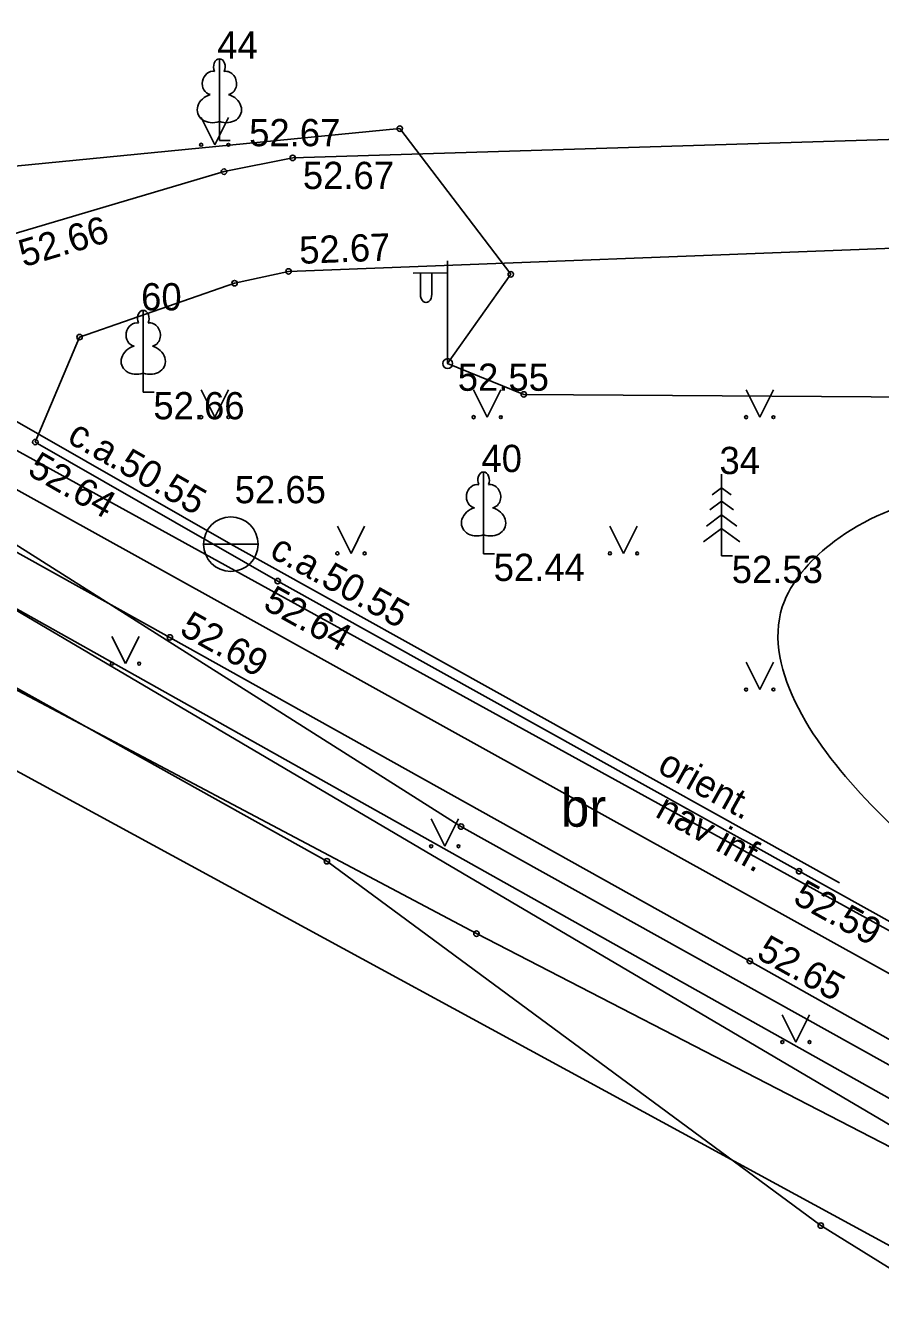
# Model space of a CAD drawing. Extents: x 619806 to 620082, y 405176 to 405386.
# Drawn here: x 619836.53 to 619852.21, y 405268.71 to 405292.19 of the extents above; entities that cross this region are included whole.
import ezdxf

# ---------------------------------------------------------------- set-up
doc = ezdxf.new("R2010")
doc.units = 0
for name, color, linetype in [('APGR_SARK_####_####_#', 7, 'Continuous'), ('APGS_ELEM_####_####_#', 7, 'Continuous'), ('APGS_VADP_ZSPR_####_#', 7, 'Continuous'), ('CELI_CMAL_####_####_#', 7, 'Continuous'), ('CELI_CSEG_####_TKST_#', 7, 'Continuous'), ('ELEK_VADP_ZSPR_####_#', 7, 'Continuous'), ('RAMI_UZMR_####_####_#', 7, 'Continuous'), ('RELJ_AATZ_####_TKST_#', 7, 'Continuous'), ('RELJ_ELEM_####_####_#', 7, 'Continuous'), ('RELJ_HORZ_PAMT_####_#', 7, 'Continuous'), ('ROBZ_UZMR_####_####_#', 7, 'Continuous'), ('SAKK_KKAN_####_####_#', 7, 'Continuous'), ('SAKT_VADP_KABE_####_#', 7, 'Continuous'), ('TERT_DIAM_####_TKST_#', 7, 'Continuous'), ('TERT_ELEM_####_####_#', 7, 'Continuous'), ('UDTK_ELEM_####_####_#', 7, 'Continuous'), ('UDTK_ELEM_####_TKST_#', 7, 'Continuous'), ('UDTK_VADP_UDEN_####_#', 7, 'Continuous'), ('UDTK_VADP_UDEN_TKST_#', 7, 'Continuous')]:
    doc.layers.add(name, color=color, linetype=linetype)

msp = doc.modelspace()

# ---------------------------------------------------------------- linework, layer by layer
at = {"layer": 'APGR_SARK_####_####_#'}
msp.add_lwpolyline([(619990.053, 405197.403), (619966.019, 405209.806), (619941.986, 405222.21), (619880.273, 405256.839), (619818.56, 405291.467)], dxfattribs=at)
at = {"layer": 'APGS_ELEM_####_####_#'}
for p, q in [((619844.273, 405285.984), (619844.273, 405287.867)), ((619844.273, 405287.651), (619843.638, 405287.646)), ((619843.773, 405287.647), (619843.773, 405287.255)), ((619843.983, 405287.649), (619843.983, 405287.255))]:
    msp.add_line(p, q, dxfattribs=at)
msp.add_circle((619844.273, 405285.984), 0.09, dxfattribs=at)
msp.add_ellipse((619843.878, 405287.255), major_axis=(0, 0.151), ratio=0.695971, start_param=1.570796, end_param=4.712389, dxfattribs=at)
at = {"layer": 'APGS_VADP_ZSPR_####_#'}
for points in [[(619889.151, 405287.633), (619888.839, 405287.188), (619868.564, 405286.313), (619868.359, 405286.853), (619868.361, 405286.315), (619854.776, 405285.354), (619845.67, 405285.418), (619844.273, 405285.984), (619845.432, 405287.623), (619843.395, 405290.297), (619835.199, 405289.5), (619828.336, 405290.779), (619827.279, 405290.766)], [(619827.279, 405290.766), (619828.233, 405290.484), (619831.689, 405284.666), (619835.137, 405280.637), (619844.802, 405275.519), (619857.367, 405269.037), (619864.044, 405264.897), (619871.373, 405258.791), (619881.17, 405253.384), (619884.232, 405252.778), (619898.622, 405244.594), (619910.805, 405239.254), (619917.273, 405236.249), (619923.426, 405231.863), (619936.8, 405224.512), (619938.618, 405223.547), (619972.929, 405204.127)]]:
    msp.add_lwpolyline(points, dxfattribs=at)
at = {"layer": 'CELI_CMAL_####_####_#'}
for points in [[(619901.141, 405301.297), (619895.285, 405291.495), (619886.767, 405291.266), (619876.357, 405290.867), (619868.929, 405290.713), (619868.879, 405291.869), (619865.764, 405291.699), (619865.807, 405290.556), (619863.458, 405290.505), (619853.554, 405290.137), (619841.43, 405289.76), (619840.169, 405289.507), (619836.17, 405288.32), (619833.502, 405287.788), (619826.905, 405297.999), (619827.372, 405299.068), (619837.906, 405304.107), (619846.534, 405308.229), (619856.914, 405313.201), (619868.255, 405318.592), (619880.738, 405324.67), (619889.516, 405328.858), (619904.867, 405336.211)], [(619859.084, 405268.056), (619860.53, 405268.999), (619849.818, 405275.016), (619839.176, 405280.957), (619830.556, 405285.755), (619828.304, 405287.001), (619823.674, 405289.625), (619822.58, 405290.149), (619821.807, 405290.092)], [(619836.706, 405284.543), (619837.518, 405286.469), (619840.363, 405287.459), (619841.354, 405287.676), (619853.093, 405288.124), (619867.164, 405288.545), (619875.272, 405288.879), (619893.318, 405289.417), (619886.606, 405285.41), (619875.838, 405278.602), (619871.198, 405275.77), (619866.813, 405272.975), (619862.385, 405270.176), (619850.722, 405276.664), (619841.154, 405281.99), (619836.706, 405284.543)]]:
    msp.add_lwpolyline(points, dxfattribs=at)
at = {"layer": 'ELEK_VADP_ZSPR_####_#'}
for points in [[(619827.133, 405291.802), (619827.743, 405291.898), (619828.762, 405290.038), (619831.425, 405286.162), (619834.68, 405283.716), (619844.517, 405277.484), (619856.454, 405270.832), (619868.451, 405264.196), (619879.269, 405258.357), (619888.402, 405252.405), (619901.725, 405245.908), (619900.354, 405242.567), (619899.734, 405241.465)], [(619827.133, 405291.802), (619827.704, 405291.789), (619828.409, 405290.12), (619829.758, 405288.499), (619829.214, 405285.683), (619831.9, 405284.021), (619834.586, 405281.015), (619842.057, 405276.848), (619851.121, 405270.16), (619862.697, 405262.983), (619874.919, 405256.089), (619882.875, 405253.63), (619881.737, 405251.572)]]:
    msp.add_lwpolyline(points, dxfattribs=at)
at = {"layer": 'RAMI_UZMR_####_####_#'}
msp.add_lwpolyline([(619874.687, 405324.979), (619926.719, 405349.544), (619966.669, 405369.042), (620021.738, 405292.03), (620049.703, 405275.476), (620026.189, 405242.287), (620012.147, 405222.917), (619996.603, 405200.928), (619989.997, 405199.173), (619982.328, 405199.155), (619922.669, 405233.014), (619882.137, 405255.756), (619859.084, 405268.056), (619820.646, 405290.715), (619813.744, 405295.206), (619820.645, 405298.752)], close=True, dxfattribs=at)
at = {"layer": 'RELJ_ELEM_####_####_#'}
for centre in [(619843.395, 405290.297), (619841.43, 405289.76), (619840.169, 405289.507), (619841.354, 405287.676), (619845.432, 405287.623), (619840.363, 405287.459), (619837.518, 405286.469), (619845.67, 405285.418), (619836.706, 405284.543), (619841.154, 405281.99), (619839.176, 405280.957), (619844.517, 405277.484), (619842.057, 405276.848), (619850.722, 405276.664), (619844.802, 405275.519), (619849.818, 405275.016), (619851.121, 405270.16)]:
    msp.add_circle(centre, 0.05, dxfattribs=at)
at = {"layer": 'RELJ_HORZ_PAMT_####_#'}
msp.add_spline([(619862.12, 405283.56), (619866.347, 405284.072), (619870.176, 405284.36), (619872.57, 405283.726), (619875.877, 405282.305), (619878.056, 405282.964), (619882.355, 405286.311), (619884.573, 405287.696), (619885.242, 405286.98), (619884.066, 405285.895), (619878.235, 405281.695), (619876.552, 405280.844), (619873.556, 405282.133), (619871.504, 405282.549), (619870.25, 405280.5), (619867.776, 405275.169), (619866.854, 405274.292), (619864.131, 405274.836), (619862.108, 405272.722), (619860.734, 405271.784), (619858.644, 405272.772), (619855.468, 405275.204), (619851.943, 405277.991), (619850.454, 405281.625), (619851.371, 405282.722), (619855.287, 405283.69), (619860.401, 405283.354), (619862.12, 405283.56)], degree=3, dxfattribs=at)
at = {"layer": 'ROBZ_UZMR_####_####_#'}
msp.add_line((619862.459, 405270.018), (619818.193, 405294.391), dxfattribs=at)
at = {"layer": 'SAKK_KKAN_####_####_#'}
msp.add_lwpolyline([(619816.151, 405294.73), (619816.825, 405294), (619832.922, 405285.576), (619895.115, 405251.073), (619918.714, 405238.138)], dxfattribs=at)
at = {"layer": 'SAKT_VADP_KABE_####_#'}
msp.add_lwpolyline([(619817.668, 405301.762), (619818.308, 405291.251), (619820.058, 405288.244), (619821.78, 405286.435), (619865.996, 405262.382), (619894.538, 405246.913), (619928.954, 405228.717), (619988.18, 405195.595)], dxfattribs=at)
at = {"layer": 'TERT_ELEM_####_####_#'}
for p, q in [((619839.75, 405290.5), (619840, 405290)), ((619840, 405290), (619840.25, 405290.5)), ((619840.084, 405290.427), (619840.084, 405290.08)), ((619840.084, 405290.08), (619840.284, 405290.08)), ((619838.687, 405285.808), (619838.687, 405285.461)), ((619838.687, 405285.461), (619838.887, 405285.461)), ((619839.75, 405285.5), (619840, 405285)), ((619840, 405285), (619840.25, 405285.5)), ((619844.75, 405285.5), (619845, 405285)), ((619845, 405285), (619845.25, 405285.5)), ((619849.75, 405285.5), (619850, 405285)), ((619850, 405285), (619850.25, 405285.5)), ((619849.301, 405283.955), (619849.301, 405282.455)), ((619849.301, 405283.705), (619849.125, 405283.577)), ((619849.301, 405283.705), (619849.475, 405283.577)), ((619849.301, 405283.455), (619849.085, 405283.297)), ((619849.301, 405283.455), (619849.517, 405283.297)), ((619849.301, 405283.205), (619849.023, 405283.001)), ((619849.301, 405283.205), (619849.579, 405283.001)), ((619842.25, 405283), (619842.5, 405282.5)), ((619842.5, 405282.5), (619842.75, 405283)), ((619844.932, 405282.84), (619844.932, 405282.493)), ((619847.25, 405283), (619847.5, 405282.5)), ((619847.5, 405282.5), (619847.75, 405283)), ((619849.301, 405282.955), (619848.969, 405282.711)), ((619849.301, 405282.955), (619849.635, 405282.711)), ((619844.932, 405282.493), (619845.132, 405282.493)), ((619849.301, 405282.455), (619849.501, 405282.455)), ((619838.111, 405280.976), (619838.361, 405280.476)), ((619838.361, 405280.476), (619838.611, 405280.976)), ((619849.75, 405280.5), (619850, 405280)), ((619850, 405280), (619850.25, 405280.5)), ((619843.971, 405277.624), (619844.221, 405277.124)), ((619844.221, 405277.124), (619844.471, 405277.624)), ((619850.414, 405274.029), (619850.664, 405273.529)), ((619850.664, 405273.529), (619850.914, 405274.029))]:
    msp.add_line(p, q, dxfattribs=at)
for points in [[(619840.084, 405291.58), (619840.084, 405290.427)], [(619840.174, 405291.348), (619840.173, 405291.349)], [(619838.687, 405286.961), (619838.687, 405285.808)], [(619838.777, 405286.729), (619838.776, 405286.73)], [(619844.932, 405283.993), (619844.932, 405282.84)], [(619845.022, 405283.761), (619845.021, 405283.762)]]:
    msp.add_lwpolyline(points, dxfattribs=at)
for centre, radius in [((619839.75, 405290), 0.028), ((619840.25, 405290), 0.0263), ((619839.75, 405285), 0.028), ((619840.25, 405285), 0.0263), ((619844.75, 405285), 0.028), ((619845.25, 405285), 0.0263), ((619849.75, 405285), 0.028), ((619850.25, 405285), 0.0263), ((619842.25, 405282.5), 0.028), ((619842.75, 405282.5), 0.0263), ((619847.25, 405282.5), 0.028), ((619847.75, 405282.5), 0.0263), ((619838.111, 405280.475), 0.028), ((619838.611, 405280.475), 0.0263), ((619849.75, 405280), 0.028), ((619850.25, 405280), 0.0263), ((619843.971, 405277.123), 0.028), ((619844.471, 405277.123), 0.0263), ((619850.414, 405273.528), 0.028), ((619850.914, 405273.528), 0.0263)]:
    msp.add_circle(centre, radius, dxfattribs=at)
for centre, major_axis, ratio, start_param, end_param in [((619840.084, 405291.43), (0, -0.15), 0.707107, 3.14537, 5.287485), ((619840.084, 405291.43), (0, -0.15), 0.707107, 0.995701, 3.137816), ((619839.956, 405291.135), (-0.039, -0.212), 0.861323, 3.141593, 6.283185), ((619840.212, 405291.135), (0.039, -0.212), 0.861323, 0, 3.141593), ((619839.994, 405290.673), (0.307, 0.095), 0.814445, 1.570796, 4.752015), ((619840.174, 405290.673), (-0.307, 0.095), 0.814445, 1.531171, 4.712389), ((619838.687, 405286.811), (0, -0.15), 0.707107, 3.14537, 5.287485), ((619838.687, 405286.811), (0, -0.15), 0.707107, 0.995701, 3.137816), ((619838.559, 405286.516), (-0.039, -0.212), 0.861323, 3.141593, 6.283185), ((619838.815, 405286.516), (0.039, -0.212), 0.861323, 0, 3.141593), ((619838.597, 405286.054), (0.307, 0.095), 0.814445, 1.570796, 4.752015), ((619838.777, 405286.054), (-0.307, 0.095), 0.814445, 1.531171, 4.712389), ((619844.804, 405283.548), (-0.039, -0.212), 0.861323, 3.141593, 6.283185), ((619844.932, 405283.843), (0, -0.15), 0.707107, 3.14537, 5.287485), ((619844.932, 405283.843), (0, -0.15), 0.707107, 0.995701, 3.137816), ((619845.06, 405283.548), (0.039, -0.212), 0.861323, 0, 3.141593), ((619844.842, 405283.086), (0.307, 0.095), 0.814445, 1.570796, 4.752015), ((619845.022, 405283.086), (-0.307, 0.095), 0.814445, 1.531171, 4.712389)]:
    msp.add_ellipse(centre, major_axis=major_axis, ratio=ratio, start_param=start_param, end_param=end_param, dxfattribs=at)
at = {"layer": 'UDTK_ELEM_####_####_#'}
msp.add_line((619839.794, 405282.668), (619840.794, 405282.668), dxfattribs=at)
msp.add_circle((619840.294, 405282.668), 0.5, dxfattribs=at)
at = {"layer": 'UDTK_VADP_UDEN_####_#'}
for points in [[(619840.294, 405282.668), (619831.461, 405287.722)], [(619840.294, 405282.668), (619851.461, 405276.454)]]:
    msp.add_lwpolyline(points, dxfattribs=at)

# ---------------------------------------------------------------- texts
at = {"layer": 'CELI_CSEG_####_TKST_#'}
msp.add_text('br', height=0.7, dxfattribs=at).set_placement((619846.352, 405277.482))
at = {"layer": 'RELJ_AATZ_####_TKST_#'}
for s, p in [(' 52.67', (619840.445, 405289.974)), (' 52.67', (619841.43, 405289.188)), (' 52.55', (619844.273, 405285.484)), (' 52.66', (619838.687, 405284.961)), (' 52.44', (619844.932, 405281.993)), (' 52.53', (619849.301, 405281.955))]:
    msp.add_text(s, height=0.5, dxfattribs=at).set_placement(p)
for s, rotation, p in [(' 52.66', 16.5322, (619836.312, 405287.698)), (' 52.67', 2.1855, (619841.373, 405287.807)), (' 52.64', 330.1456, (619836.377, 405284.05)), (' 52.64', 330.8976, (619840.699, 405281.587)), (' 52.69', 330.8271, (619839.168, 405281.118)), (' 52.59', 330.9133, (619850.424, 405276.185)), (' 52.65', 330.6768, (619849.754, 405275.174))]:
    msp.add_text(s, height=0.5, rotation=rotation, dxfattribs=at).set_placement(p)
at = {"layer": 'TERT_DIAM_####_TKST_#'}
for s, p in [(' 44', (619839.859, 405291.58)), (' 60', (619838.462, 405286.961)), (' 40', (619844.707, 405283.993)), (' 34', (619849.076, 405283.955))]:
    msp.add_text(s, height=0.5, dxfattribs=at).set_placement(p)
at = {"layer": 'UDTK_ELEM_####_TKST_#'}
msp.add_text('52.65', height=0.5, dxfattribs=at).set_placement((619840.365, 405283.42))
at = {"layer": 'UDTK_VADP_UDEN_TKST_#'}
for s, rotation, p in [('c.a.50.55', 330.2237, (619837.266, 405284.553)), ('c.a.50.55', 330.906, (619840.98, 405282.449)), ('orient.', 330.906, (619848.097, 405278.498)), ('nav inf.', 330.906, (619848.059, 405277.677))]:
    msp.add_text(s, height=0.5, rotation=rotation, dxfattribs=at).set_placement(p)

doc.saveas('drawing.dxf')
